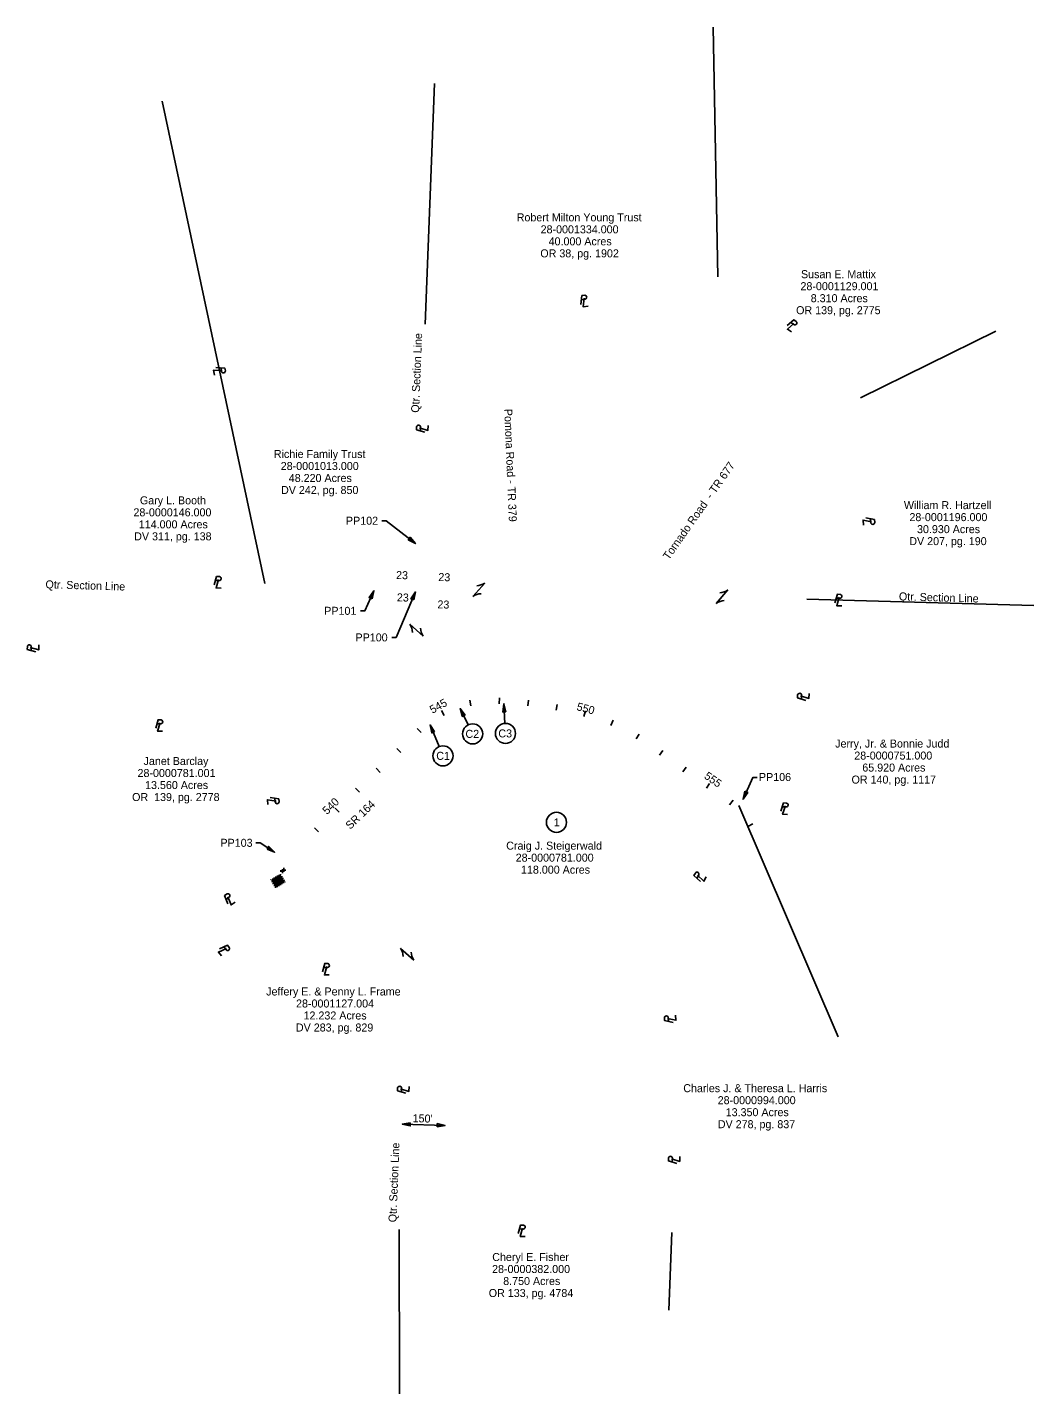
# Model space of a CAD drawing. Extents: x 218385 to 335869, y 428020 to 438981.
# Drawn here: x 218385 to 221906, y 434201 to 438981 of the extents above; entities that cross this region are included whole.
import ezdxf

# ---------------------------------------------------------------- set-up
doc = ezdxf.new("R2010")
doc.units = 0
for name, color, linetype in [('DV_X_Property_Line', 7, 'Continuous'), ('RW_X_CL_100_Stations', 7, 'Continuous'), ('RW_X_Esmt_U', 7, 'Continuous'), ('SH_Text', 7, 'Continuous')]:
    doc.layers.add(name, color=color, linetype=linetype)

msp = doc.modelspace()

# ---------------------------------------------------------------- linework, layer by layer
at = {"layer": 'DV_X_Property_Line'}
for p, q in [((220800.8, 438109), (220785, 438981.4)), ((219777.7, 437943.4), (219810.4, 438785.3)), ((219216.6, 437035.1), (218856.6, 438723.4)), ((220323.8, 438028.5), (220336.7, 438030.3)), ((220332.7, 438023.4), (220332.7, 438023.4)), ((221056.6, 437948.6), (221067.4, 437941.5)), ((221059.8, 437939), (221059.8, 437939)), ((221299.8, 437685.3), (221774.2, 437918.4)), ((219061.9, 437790.1), (219064.6, 437777.4)), ((219057.5, 437781), (219057.5, 437781)), ((219760.7, 437569.3), (219761.1, 437582.2)), ((219767.2, 437577.1), (219767.2, 437577.1)), ((221329.7, 437253.2), (221329.7, 437253.2)), ((221335.3, 437261.7), (221336.2, 437248.7)), ((219043.7, 437046.2), (219056.6, 437045.9)), ((219051.5, 437039.8), (219051.5, 437039.8)), ((219944.6, 436990.3), (219986, 437037.1)), ((219965.3, 437013.7), (219965.3, 437013.7)), ((220795.3, 436966), (220836.6, 437012.8)), ((220815.9, 436989.4), (220815.9, 436989.4)), ((221112.4, 436980.9), (221906.2, 436958.2)), ((221215.3, 436984.2), (221228.3, 436983.8)), ((221223.1, 436977.7), (221223.1, 436977.7)), ((219770.3, 436851.3), (219723.5, 436892.7)), ((219746.9, 436872), (219746.9, 436872)), ((218399.1, 436800.8), (218399.3, 436813.8)), ((218405.5, 436808.7), (218405.5, 436808.7)), ((221093.5, 436631.4), (221094, 436644.3)), ((221100, 436639.2), (221100, 436639.2)), ((218839.1, 436545.1), (218852.1, 436544.7)), ((218847, 436538.6), (218847, 436538.6)), ((219245.9, 436275.8), (219245.9, 436275.8)), ((219251.3, 436284.3), (219252.5, 436271.4)), ((220875.2, 436259.1), (221222.7, 435449)), ((221026.9, 436254.6), (221039.8, 436253.6)), ((221034.4, 436247.8), (221034.4, 436247.8)), ((220728.1, 436003.8), (220734.3, 436015.1)), ((220737.4, 436007.8), (220737.4, 436007.8)), ((219080.8, 435930.2), (219091.3, 435937.9)), ((219091, 435929.9), (219091, 435929.9)), ((219072.6, 435764.6), (219080.7, 435754.5)), ((219072.7, 435754.4), (219072.7, 435754.4)), ((219737.7, 435717.7), (219690.9, 435759)), ((219714.3, 435738.4), (219714.3, 435738.4)), ((219422.3, 435692.5), (219435.3, 435692.2)), ((219430.2, 435686.1), (219430.2, 435686.1)), ((220628.6, 435503.3), (220627.8, 435516.2)), ((220634.4, 435511.7), (220634.4, 435511.7)), ((219694.2, 435256.5), (219694.5, 435269.5)), ((219700.6, 435264.4), (219700.6, 435264.4)), ((220641.7, 435011.5), (220642.1, 435024.5)), ((220648.2, 435019.3), (220648.2, 435019.3)), ((220107.6, 434777.3), (220120.5, 434777.1)), ((219686.6, 434775.8), (219687, 434201)), ((220115.5, 434771), (220115.5, 434771)), ((220640.1, 434765), (220629.2, 434492.7))]:
    msp.add_line(p, q, dxfattribs=at)
for points in [[(220322, 438012.1), (220325.5, 438042.6), (220335.7, 438044)], [(220333.9, 438033.3), (220330.3, 438002.9), (220347.6, 438005.4)], [(221044.3, 437937.6), (221067.1, 437958.1), (221075.8, 437952.4)], [(221067.3, 437945.5), (221044.5, 437925.2), (221059.1, 437915.6)], [(219045.5, 437790.9), (219076.1, 437789.4), (219078.3, 437779.3)], [(219067.5, 437780.4), (219036.9, 437781.9), (219040.5, 437764.9)], [(219776.5, 437564.6), (219747.1, 437573.3), (219747.4, 437583.6)], [(219757.7, 437580.1), (219787, 437571.3), (219787.5, 437588.8)], [(221319.2, 437264.8), (221349.3, 437259), (221350, 437248.7)], [(221339.4, 437251.2), (221309.4, 437257.1), (221310.6, 437239.7)], [(219039, 437030.4), (219047.7, 437059.9), (219058, 437059.5)], [(219054.4, 437049.3), (219045.7, 437020), (219063.1, 437019.5)], [(221210.7, 436968.4), (221219.3, 436997.8), (221229.6, 436997.5)], [(221226.1, 436987.3), (221217.3, 436957.9), (221234.8, 436957.4)], [(218414.9, 436796.4), (218385.4, 436804.6), (218385.6, 436815)], [(218395.9, 436811.5), (218425.3, 436803.2), (218425.6, 436820.6)], [(221109.2, 436626.6), (221079.9, 436635.5), (221080.3, 436645.8)], [(221090.5, 436642.2), (221119.8, 436633.2), (221120.4, 436650.7)], [(218834.5, 436529.3), (218843.1, 436558.7), (218853.5, 436558.4)], [(218849.9, 436548.1), (218841.1, 436518.8), (218858.6, 436518.3)], [(219255.7, 436274), (219225.5, 436279.2), (219227.1, 436261.8)], [(219235.1, 436287.1), (219265.3, 436282), (219266.3, 436271.7)], [(221021.6, 436239), (221031.5, 436268), (221041.8, 436267.3)], [(221037.8, 436257.2), (221027.8, 436228.2), (221045.2, 436227)], [(220740.1, 435992.4), (220717.8, 436013.5), (220722.8, 436022.6)], [(220730.3, 436014.7), (220752.4, 435993.6), (220760.8, 436008.9)], [(219086.8, 435914.9), (219075.6, 435943.4), (219084, 435949.5)], [(219087.4, 435939.2), (219098.5, 435910.7), (219112.6, 435921)], [(219081.9, 435758.4), (219053.9, 435746.1), (219064.8, 435732.4)], [(219057.5, 435757.9), (219085.6, 435770.3), (219092, 435762.3)], [(219417.8, 435676.7), (219426.2, 435706.2), (219436.5, 435705.9)], [(219433, 435695.7), (219424.6, 435666.2), (219442, 435665.9)], [(220644.7, 435500), (220614.7, 435506.1), (220614.1, 435516.4)], [(220624.6, 435513.8), (220654.6, 435507.6), (220653.6, 435525)], [(219710, 435251.9), (219680.6, 435260.6), (219680.9, 435270.9)], [(219691.1, 435267.3), (219720.4, 435258.6), (219720.9, 435276)], [(220657.5, 435006.8), (220628.1, 435015.6), (220628.4, 435025.9)], [(220638.7, 435022.3), (220668, 435013.4), (220668.5, 435030.9)], [(220103.2, 434761.4), (220111.3, 434791), (220121.7, 434790.8)], [(220118.3, 434780.5), (220110, 434751.1), (220127.5, 434750.9)]]:
    msp.add_lwpolyline(points, dxfattribs=at)
for centre, radius, start, end in [((220335.6, 438037.1), 6.9, 278.6763, 89.5334), ((221071.1, 437947.3), 6.9, 237.1958, 48.0529), ((219071.4, 437778.9), 6.9, 192.5077, 3.3649), ((219754.2, 437582.4), 6.9, 358.8222, 169.6793), ((221343.1, 437249.3), 6.9, 184.4319, 355.289), ((219056.8, 437052.8), 6.9, 268.8347, 79.6918), ((219955.6, 437081), 53.4, 272.0582, 304.7008), ((219975, 436946.4), 53.4, 92.0582, 124.7008), ((220825.7, 436922.1), 53.4, 92.0582, 124.7008), ((220806.2, 437056.7), 53.4, 272.0582, 304.7008), ((221228.4, 436990.7), 6.9, 268.8347, 79.6918), ((219679.6, 436862.3), 53.4, 2.0466, 34.6892), ((219814.2, 436881.7), 53.4, 182.0466, 214.6892), ((218392.4, 436813.8), 6.9, 359.593, 170.4501), ((221087.1, 436644.5), 6.9, 358.393, 169.2501), ((218852.2, 436551.6), 6.9, 268.8347, 79.6918), ((219259.4, 436272.1), 6.9, 185.6513, 356.5084), ((221040.3, 436260.5), 6.9, 266.3944, 77.2515), ((220728.3, 436018.4), 6.9, 331.7638, 142.6209), ((219087.2, 435943.4), 6.9, 306.6513, 117.5084), ((219086.1, 435758.8), 6.9, 219.0958, 29.9529), ((219647, 435728.7), 53.4, 2.0466, 34.6892), ((219781.6, 435748.1), 53.4, 182.0466, 214.6892), ((219435.3, 435699.1), 6.9, 269.3777, 80.2348), ((220621, 435515.8), 6.9, 3.8221, 174.6793), ((219687.7, 435269.6), 6.9, 358.8222, 169.6793), ((220635.2, 435024.6), 6.9, 358.6499, 169.507), ((220120.5, 434784), 6.9, 269.8221, 80.6793)]:
    msp.add_arc(centre, radius, start, end, dxfattribs=at)
at = {"layer": 'RW_X_CL_100_Stations'}
for p, q in [((219937, 436607.8), (219933, 436627.4)), ((220036.6, 436615), (220036.8, 436635)), ((220136.2, 436607.3), (220139, 436627.1)), ((220235.1, 436592.4), (220238.6, 436612)), ((219843.6, 436573.2), (219833.9, 436590.7)), ((220332.6, 436570.5), (220337.8, 436589.9)), ((220427.4, 436538.9), (220435.3, 436557.3)), ((219763.6, 436513.7), (219749.7, 436528.1)), ((220515.5, 436491.8), (220526.4, 436508.6)), ((219691.7, 436444.2), (219677.8, 436458.6)), ((220597.4, 436434.6), (220609, 436450.9)), ((219619.9, 436374.7), (219606, 436389)), ((220679.3, 436377), (220690.8, 436393.4)), ((219548, 436305.1), (219534.1, 436319.5)), ((220761.1, 436319.5), (220772.6, 436335.9)), ((220842.5, 436261.5), (220855.1, 436277.1)), ((219476.1, 436235.6), (219462.2, 436250)), ((219404.2, 436166.1), (219390.3, 436180.4)), ((220906.5, 436185.5), (220923.9, 436195.2))]:
    msp.add_line(p, q, dxfattribs=at)
at = {"layer": 'RW_X_Esmt_U'}
for p, q in [((219272.8, 436026.6), (219272.9, 436032)), ((219277.7, 436022.5), (219278, 436036.2)), ((219282.8, 436026.7), (219283.1, 436040.6)), ((219287.9, 436030.8), (219287.9, 436034.7)), ((219237.9, 435997.1), (219238.4, 436000.1)), ((219241.9, 435990.4), (219243.9, 436003.4)), ((219245.9, 435983.7), (219249.5, 436006.8)), ((219249.9, 435976.9), (219255.1, 436010.1)), ((219254, 435970.2), (219260.7, 436013.4)), ((219259.5, 435973.6), (219266.3, 436016.8)), ((219265.1, 435976.9), (219271.6, 436018.8)), ((219270.7, 435980.3), (219275.7, 436012.1)), ((219276.3, 435983.6), (219279.7, 436005.4)), ((219281.9, 435987), (219283.7, 435998.7)), ((219287.4, 435990.3), (219287.7, 435992))]:
    msp.add_line(p, q, dxfattribs=at)
at = {"layer": 'SH_Text'}
for p, q in [((219927.9, 436540.9), (219899.8, 436597.9)), ((220056.5, 436546.1), (220052.8, 436614.6)), ((219826.1, 436464.9), (219794.6, 436540.8)), ((219697.2, 435144), (219847.1, 435139.7))]:
    msp.add_line(p, q, dxfattribs=at)
for points in [[(219625.9, 437255.2), (219641.2, 437255.2), (219743.1, 437175.4)], [(219551.4, 436940.2), (219566.7, 436940.2), (219597.7, 437010)], [(219660.3, 436847), (219675.7, 436847), (219743.3, 437005.9)], [(220939.2, 436356.9), (220923.9, 436356.9), (220889.3, 436280.7)], [(219184.8, 436128.5), (219200.1, 436128.5), (219250.6, 436095.5)]]:
    msp.add_lwpolyline(points, dxfattribs=at)
for points in [[(219717.6, 437188.2), (219724.5, 437197.1), (219743.1, 437175.4)], [(219591.4, 436982.1), (219581.2, 436986.6), (219597.7, 437010)], [(219737.5, 436978), (219727.2, 436982.4), (219743.3, 437005.9)], [(219917.2, 436575.2), (219907.1, 436570.3), (219899.8, 436597.9)], [(220059.9, 436586.9), (220048.7, 436586.3), (220052.8, 436614.6)], [(219810.5, 436517.1), (219800.2, 436512.8), (219794.6, 436540.8)], [(220895.8, 436308.5), (220906, 436303.9), (220889.3, 436280.7)], [(219224.1, 436106.1), (219230.3, 436115.5), (219250.6, 436095.5)], [(219725.3, 435148.8), (219725, 435137.6), (219697.2, 435144)], [(219818.9, 435134.9), (219819.3, 435146.1), (219847.1, 435139.7)]]:
    msp.add_lwpolyline(points, close=True, dxfattribs=at)
for centre in [(220058.3, 436511), (219943.4, 436509.4), (219839.6, 436432.5), (220236.6, 436199.9)]:
    msp.add_circle(centre, 35.1, dxfattribs=at)

# ---------------------------------------------------------------- texts
at = {"layer": 'DV_X_Property_Line'}
for rotation, p in [(87.7747, (219756, 437632.5)), (358.3637, (218448.6, 437018.8)), (358.3637, (221434.4, 436976.7)), (87.7747, (219676.7, 434800.1))]:
    msp.add_text('Qtr. Section Line', height=28, rotation=rotation, dxfattribs=at).set_placement(p)
at = {"layer": 'SH_Text'}
for s, p in [('Robert Milton Young Trust', (220097.6, 438302.6)), ('28-0001334.000', (220181.2, 438260.6)), ('40.000 Acres', (220209.2, 438218.6)), ('OR 38, pg. 1902', (220180.2, 438176.6)), ('Susan E. Mattix', (221092.1, 438103.7)), ('28-0001129.001', (221090.3, 438061.7)), ('8.310 Acres', (221126.2, 438019.7)), ('OR 139, pg. 2775', (221075.1, 437977.7)), ('Richie Family Trust', (219247.9, 437474.6)), ('28-0001013.000', (219272, 437432.6)), ('48.220 Acres', (219300.1, 437390.6)), ('DV 242, pg. 850', (219273.1, 437348.6)), ('Gary L. Booth', (218779.3, 437312.5)), ('William R. Hartzell', (221452.2, 437295.7)), ('28-0000146.000', (218756.7, 437270.5)), ('PP102', (219500.1, 437241.2)), ('28-0001196.000', (221471.5, 437253.7)), ('DV 311, pg. 138', (218759.3, 437186.5)), ('114.000 Acres', (218775.4, 437228.5)), ('30.930 Acres', (221498.1, 437211.7)), ('DV 207, pg. 190', (221471.1, 437169.7)), ('PP101', (219424.2, 436925.9)), ('PP100', (219533.6, 436832.9)), ('C2', (219918.3, 436495.4)), ('C3', (220033.3, 436497)), ('Jerry, Jr. & Bonnie Judd', (221211.7, 436461.5)), ('Janet Barclay', (218792.2, 436400.4)), ('C1', (219816.1, 436418.5)), ('28-0000751.000', (221278.6, 436419.5)), ('65.920 Acres', (221306.7, 436377.5)), ('28-0000781.001', (218771, 436358.4)), ('PP106', (220945, 436344.4)), ('OR 140, pg. 1117', (221269, 436335.5)), ('13.560 Acres', (218797.4, 436316.4)), ('OR  139, pg. 2778', (218752, 436274.4)), ('1', (220227.2, 436185.9)), ('PP103', (219061.1, 436114.3)), ('Craig J. Steigerwald', (220060.8, 436104.3)), ('28-0000781.000', (220094, 436062.3)), ('118.000 Acres', (220112.6, 436020.3)), ('Jeffery E. & Penny L. Frame', (219221.1, 435594.1)), ('28-0001127.004', (219325.6, 435552.1)), ('DV 283, pg. 829', (219325.1, 435468.1)), ('12.232 Acres', (219351.8, 435510.1)), ('Charles J. & Theresa L. Harris', (220680.3, 435255.8)), ('28-0000994.000', (220800.7, 435213.8)), ('13.350 Acres', (220828.8, 435171.8)), ('DV 278, pg. 837', (220801.2, 435129.8)), ('Cheryl E. Fisher', (220012, 434665.1)), ('28-0000382.000', (220011.4, 434623.1)), ('8.750 Acres', (220050.3, 434581.1)), ('OR 133, pg. 4784', (219999.8, 434539.1))]:
    msp.add_text(s, height=28, dxfattribs=at).set_placement(p)
for s, rotation, p in [('Pomona Road - TR 379', 272.3588, (220053.9, 437646)), ('Tornado Road  - TR 677', 54.9915, (220629.6, 437115.9)), ('23', 358.3638, (219675.2, 437051.4)), ('23', 358.3638, (219823.1, 437044.3)), ('23', 358.3638, (219678, 436973.3)), ('23', 358.3638, (219819.9, 436948.7)), ('545', 29.0185, (219802.7, 436579.4)), ('550', 345.1048, (220305.3, 436592.8)), ('555', 324.8891, (220751, 436356)), ('540', 44.0508, (219434, 436225.2)), ('SR 164', 43.9093, (219515, 436173.3)), ("150'", 358.3521, (219733.1, 435151))]:
    msp.add_text(s, height=28, rotation=rotation, dxfattribs=at).set_placement(p)

doc.saveas('drawing.dxf')
